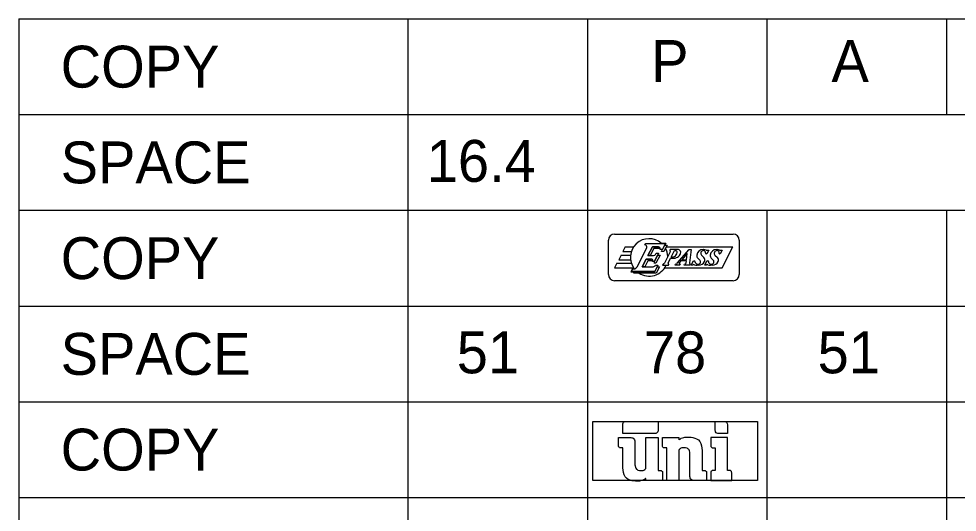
# Model space of a CAD drawing. Extents: x 10268259 to 10268554, y 2141099 to 2141249.
# Drawn here: x 10268318.48 to 10268334.16, y 2141164.78 to 2141173.03 of the extents above; entities that cross this region are included whole.
import ezdxf

# ---------------------------------------------------------------- set-up
doc = ezdxf.new("R2010")
doc.units = 0
for name, color, linetype in [('60', 7, 'Continuous'), ('61', 7, 'Continuous'), ('62', 7, 'Continuous'), ('Default', 7, 'Continuous'), ('GSSign', 7, 'Continuous'), ('TextMisc', 7, 'Continuous')]:
    doc.layers.add(name, color=color, linetype=linetype)

# ---------------------------------------------------------------- blocks, each defined once
blk = doc.blocks.new('block 2_2')
at = {"layer": 'Default'}
for points in [[(19.1, -34.5), (14.6, -34.5), (11, -38.1), (11, -42.5), (11, -42.5), (11, -64.2), (11, -64.2), (11, -64.2), (89.5, -64.2), (89.5, -64.2), (94.1, -64.2), (97.9, -60.4), (97.9, -55.8), (97.9, -55.8), (97.9, -34.5), (97.9, -34.5), (97.9, -34.5), (19.1, -34.5), (19.1, -34.5)], [(19.1, -34.5), (14.6, -34.5), (11, -38.1), (11, -42.5), (11, -42.5), (11, -64.2), (11, -64.2), (11, -64.2), (89.5, -64.2), (89.5, -64.2), (94.1, -64.2), (97.9, -60.4), (97.9, -55.8), (97.9, -55.8), (97.9, -34.5), (97.9, -34.5), (97.9, -34.5), (19.1, -34.5), (19.1, -34.5)], [(268.4, -42.6), (268.4, -38.2), (264.8, -34.5), (260.3, -34.5), (260.3, -34.5), (238.7, -34.5), (238.7, -34.5), (238.7, -34.5), (238.7, -55.9), (238.7, -55.9), (238.7, -60.5), (242.4, -64.3), (247.1, -64.3), (247.1, -64.3), (268.4, -64.3), (268.4, -64.3), (268.4, -64.3), (268.4, -42.6), (268.4, -42.6)], [(268.4, -42.6), (268.4, -38.2), (264.8, -34.5), (260.3, -34.5), (260.3, -34.5), (238.7, -34.5), (238.7, -34.5), (238.7, -34.5), (238.7, -55.9), (238.7, -55.9), (238.7, -60.5), (242.4, -64.3), (247.1, -64.3), (247.1, -64.3), (268.4, -64.3), (268.4, -64.3), (268.4, -64.3), (268.4, -42.6), (268.4, -42.6)], [(97.9, -74.6), (97.9, -74.6), (68, -74.6), (68, -74.6), (68, -74.6), (68, -74.6), (68, -74.6), (68, -74.6), (68, -150.1), (68, -150.1), (65.2, -153.3), (61, -155.4), (56.3, -155.4), (47.8, -155.4), (40.9, -148.5), (40.9, -139.9), (40.9, -139.6), (40.9, -138.9), (40.9, -138.9), (40.9, -138.9), (40.9, -85.6), (40.9, -85.6), (40.9, -79.5), (36, -74.6), (29.9, -74.6), (29.9, -74.6), (12.8, -74.6), (12.8, -74.6), (12.8, -74.6), (11, -74.6), (11, -74.6), (11, -74.6), (0, -74.6), (0, -74.6), (0, -74.6), (0, -93), (0, -93), (0, -96.8), (3.1, -99.8), (6.9, -99.8), (6.9, -99.8), (11, -99.8), (11, -99.8), (11, -99.8), (11, -138.9), (11, -138.9), (11, -138.9), (11.1, -138.9), (11.1, -138.9), (11.1, -169.3), (28.5, -181.4), (48.5, -181.4), (55.6, -181.4), (62.3, -179), (68, -174.8), (68, -174.8), (68, -180.3), (68, -180.3), (68, -180.3), (108.9, -180.3), (108.9, -180.3), (108.9, -180.3), (108.9, -161.9), (108.9, -161.9), (108.9, -158.1), (105.8, -155.1), (102, -155.1), (102, -155.1), (97.9, -155.1), (97.9, -155.1), (97.9, -155.1), (97.9, -74.6), (97.9, -74.6)], [(97.9, -74.6), (97.9, -74.6), (68, -74.6), (68, -74.6), (68, -74.6), (68, -74.6), (68, -74.6), (68, -74.6), (68, -150.1), (68, -150.1), (65.2, -153.3), (61, -155.4), (56.3, -155.4), (47.8, -155.4), (40.9, -148.5), (40.9, -139.9), (40.9, -139.6), (40.9, -138.9), (40.9, -138.9), (40.9, -138.9), (40.9, -85.6), (40.9, -85.6), (40.9, -79.5), (36, -74.6), (29.9, -74.6), (29.9, -74.6), (12.8, -74.6), (12.8, -74.6), (12.8, -74.6), (11, -74.6), (11, -74.6), (11, -74.6), (0, -74.6), (0, -74.6), (0, -74.6), (0, -93), (0, -93), (0, -96.8), (3.1, -99.8), (6.9, -99.8), (6.9, -99.8), (11, -99.8), (11, -99.8), (11, -99.8), (11, -138.9), (11, -138.9), (11, -138.9), (11.1, -138.9), (11.1, -138.9), (11.1, -169.3), (28.5, -181.4), (48.5, -181.4), (55.6, -181.4), (62.3, -179), (68, -174.8), (68, -174.8), (68, -180.3), (68, -180.3), (68, -180.3), (108.9, -180.3), (108.9, -180.3), (108.9, -180.3), (108.9, -161.9), (108.9, -161.9), (108.9, -158.1), (105.8, -155.1), (102, -155.1), (102, -155.1), (97.9, -155.1), (97.9, -155.1), (97.9, -155.1), (97.9, -74.6), (97.9, -74.6)], [(119.3, -155.1), (119.3, -155.1), (119.3, -180.3), (119.3, -180.3), (119.3, -180.3), (149.1, -180.3), (149.1, -180.3), (149.1, -180.3), (149.1, -180.3), (149.1, -180.3), (149.1, -180.3), (149.1, -155.1), (149.1, -155.1), (149.1, -155.1), (149.1, -104.8), (149.1, -104.8), (152, -101.6), (156.1, -99.5), (160.8, -99.5), (169.3, -99.5), (176.3, -106.4), (176.3, -115), (176.3, -115.3), (176.3, -116), (176.3, -116), (176.3, -116), (176.3, -169.3), (176.3, -169.3), (176.3, -175.4), (181.2, -180.3), (187.3, -180.3), (187.3, -180.3), (204.3, -180.3), (204.3, -180.3), (204.3, -180.3), (206.1, -180.3), (206.1, -180.3), (206.1, -180.3), (217.1, -180.3), (217.1, -180.3), (217.1, -180.3), (217.1, -161.9), (217.1, -161.9), (217.1, -158.1), (214.1, -155.1), (210.3, -155.1), (210.3, -155.1), (206.1, -155.1), (206.1, -155.1), (206.1, -155.1), (206.1, -116), (206.1, -116), (206.1, -116), (206, -116), (206, -116), (206, -85.6), (188.7, -73.5), (168.7, -73.5), (161.5, -73.5), (154.8, -75.9), (149.1, -80.1), (149.1, -80.1), (149.1, -74.6), (149.1, -74.6), (149.1, -74.6), (119.3, -74.6), (119.3, -74.6), (119.3, -74.6), (108.3, -74.6), (108.3, -74.6), (108.3, -74.6), (108.3, -93), (108.3, -93), (108.3, -96.8), (111.3, -99.8), (115.1, -99.8), (115.1, -99.8), (119.3, -99.8), (119.3, -99.8), (119.3, -99.8), (119.3, -104.7), (119.3, -104.7), (119.3, -104.7), (119.3, -155.1), (119.3, -155.1)], [(119.3, -155.1), (119.3, -155.1), (119.3, -180.3), (119.3, -180.3), (119.3, -180.3), (149.1, -180.3), (149.1, -180.3), (149.1, -180.3), (149.1, -180.3), (149.1, -180.3), (149.1, -180.3), (149.1, -155.1), (149.1, -155.1), (149.1, -155.1), (149.1, -104.8), (149.1, -104.8), (152, -101.6), (156.1, -99.5), (160.8, -99.5), (169.3, -99.5), (176.3, -106.4), (176.3, -115), (176.3, -115.3), (176.3, -116), (176.3, -116), (176.3, -116), (176.3, -169.3), (176.3, -169.3), (176.3, -175.4), (181.2, -180.3), (187.3, -180.3), (187.3, -180.3), (204.3, -180.3), (204.3, -180.3), (204.3, -180.3), (206.1, -180.3), (206.1, -180.3), (206.1, -180.3), (217.1, -180.3), (217.1, -180.3), (217.1, -180.3), (217.1, -161.9), (217.1, -161.9), (217.1, -158.1), (214.1, -155.1), (210.3, -155.1), (210.3, -155.1), (206.1, -155.1), (206.1, -155.1), (206.1, -155.1), (206.1, -116), (206.1, -116), (206.1, -116), (206, -116), (206, -116), (206, -85.6), (188.7, -73.5), (168.7, -73.5), (161.5, -73.5), (154.8, -75.9), (149.1, -80.1), (149.1, -80.1), (149.1, -74.6), (149.1, -74.6), (149.1, -74.6), (119.3, -74.6), (119.3, -74.6), (119.3, -74.6), (108.3, -74.6), (108.3, -74.6), (108.3, -74.6), (108.3, -93), (108.3, -93), (108.3, -96.8), (111.3, -99.8), (115.1, -99.8), (115.1, -99.8), (119.3, -99.8), (119.3, -99.8), (119.3, -99.8), (119.3, -104.7), (119.3, -104.7), (119.3, -104.7), (119.3, -155.1), (119.3, -155.1)], [(279.4, -161.9), (279.4, -161.9), (279.4, -180.3), (279.4, -180.3), (279.4, -180.3), (227.5, -180.3), (227.5, -180.3), (227.5, -180.3), (227.5, -161.9), (227.5, -161.9), (227.5, -158.1), (230.6, -155.1), (234.4, -155.1), (234.4, -155.1), (238.5, -155.1), (238.5, -155.1), (238.5, -155.1), (238.5, -104.7), (238.5, -104.7), (238.5, -104.7), (238.5, -99.8), (238.5, -99.8), (238.5, -99.8), (234.4, -99.8), (234.4, -99.8), (230.6, -99.8), (227.5, -96.8), (227.5, -93), (227.5, -93), (227.5, -74.6), (227.5, -74.6), (227.5, -74.6), (238.5, -74.6), (238.5, -74.6), (238.5, -74.6), (268.4, -74.6), (268.4, -74.6), (268.4, -74.6), (268.4, -82), (268.4, -82), (268.4, -82), (268.4, -155.1), (268.4, -155.1), (268.4, -155.1), (272.5, -155.1), (272.5, -155.1), (276.3, -155.1), (279.4, -158.1), (279.4, -161.9)], [(279.4, -161.9), (279.4, -161.9), (279.4, -180.3), (279.4, -180.3), (279.4, -180.3), (227.5, -180.3), (227.5, -180.3), (227.5, -180.3), (227.5, -161.9), (227.5, -161.9), (227.5, -158.1), (230.6, -155.1), (234.4, -155.1), (234.4, -155.1), (238.5, -155.1), (238.5, -155.1), (238.5, -155.1), (238.5, -104.7), (238.5, -104.7), (238.5, -104.7), (238.5, -99.8), (238.5, -99.8), (238.5, -99.8), (234.4, -99.8), (234.4, -99.8), (230.6, -99.8), (227.5, -96.8), (227.5, -93), (227.5, -93), (227.5, -74.6), (227.5, -74.6), (227.5, -74.6), (238.5, -74.6), (238.5, -74.6), (238.5, -74.6), (268.4, -74.6), (268.4, -74.6), (268.4, -74.6), (268.4, -82), (268.4, -82), (268.4, -82), (268.4, -155.1), (268.4, -155.1), (268.4, -155.1), (272.5, -155.1), (272.5, -155.1), (276.3, -155.1), (279.4, -158.1), (279.4, -161.9)]]:
    blk.add_open_spline(points, degree=3, dxfattribs=at)

msp = doc.modelspace()

# ---------------------------------------------------------------- linework, layer by layer
at = {"layer": '60'}
for p, q in [((10268318.48, 2141173.028), (10268393.98, 2141173.028)), ((10268318.48, 2141173.028), (10268318.48, 2141157.028)), ((10268324.98, 2141173.028), (10268324.98, 2141157.028)), ((10268327.98, 2141173.028), (10268327.98, 2141157.028)), ((10268330.98, 2141173.028), (10268330.98, 2141171.428)), ((10268333.98, 2141173.028), (10268333.98, 2141171.428)), ((10268318.48, 2141169.828), (10268393.98, 2141169.828)), ((10268330.98, 2141169.828), (10268330.98, 2141166.628)), ((10268333.98, 2141169.828), (10268333.98, 2141166.628)), ((10268318.48, 2141166.628), (10268393.98, 2141166.628)), ((10268330.98, 2141166.628), (10268330.98, 2141163.428)), ((10268333.98, 2141166.628), (10268333.98, 2141163.428))]:
    msp.add_line(p, q, dxfattribs=at)
at = {"layer": '61'}
for p, q in [((10268318.48, 2141171.428), (10268393.98, 2141171.428)), ((10268318.48, 2141168.228), (10268393.98, 2141168.228)), ((10268318.48, 2141165.028), (10268393.98, 2141165.028))]:
    msp.add_line(p, q, dxfattribs=at)
at = {"layer": '62'}
for p, q in [((10268328.435, 2141169.431), (10268330.414, 2141169.431)), ((10268328.331, 2141168.754), (10268328.331, 2141169.327)), ((10268328.614, 2141169.216), (10268328.574, 2141169.138)), ((10268328.614, 2141169.216), (10268328.754, 2141169.216)), ((10268328.811, 2141168.884), (10268328.973, 2141169.202)), ((10268328.942, 2141169.248), (10268328.955, 2141169.275)), ((10268328.955, 2141169.275), (10268329.287, 2141169.275)), ((10268329.068, 2141169.216), (10268328.993, 2141169.07)), ((10268328.993, 2141169.07), (10268329.068, 2141169.216)), ((10268328.993, 2141169.07), (10268329.068, 2141169.216)), ((10268329.167, 2141169.216), (10268329.068, 2141169.216)), ((10268329.068, 2141169.216), (10268329.167, 2141169.216)), ((10268329.068, 2141169.216), (10268329.167, 2141169.216)), ((10268329.216, 2141169.278), (10268329.292, 2141169.278)), ((10268329.287, 2141169.275), (10268329.234, 2141169.17)), ((10268329.234, 2141169.17), (10268329.272, 2141169.245)), ((10268329.234, 2141169.17), (10268329.272, 2141169.245)), ((10268329.312, 2141169.245), (10268329.258, 2141169.141)), ((10268329.312, 2141169.245), (10268329.258, 2141169.141)), ((10268329.272, 2141169.245), (10268329.312, 2141169.245)), ((10268329.272, 2141169.245), (10268329.312, 2141169.245)), ((10268329.292, 2141169.278), (10268329.275, 2141169.245)), ((10268329.297, 2141169.216), (10268330.411, 2141169.216)), ((10268330.232, 2141168.864), (10268330.411, 2141169.216)), ((10268330.518, 2141169.327), (10268330.518, 2141168.754)), ((10268328.544, 2141169.079), (10268328.505, 2141169.001)), ((10268328.544, 2141169.079), (10268328.702, 2141169.079)), ((10268328.574, 2141169.138), (10268328.716, 2141169.138)), ((10268328.993, 2141169.07), (10268329.086, 2141169.07)), ((10268329.032, 2141169.07), (10268328.993, 2141169.07)), ((10268329.032, 2141169.07), (10268328.993, 2141169.07)), ((10268329.092, 2141169.187), (10268329.032, 2141169.07)), ((10268329.092, 2141169.187), (10268329.032, 2141169.07)), ((10268329.198, 2141169.187), (10268329.092, 2141169.187)), ((10268329.198, 2141169.187), (10268329.092, 2141169.187)), ((10268329.169, 2141169.109), (10268329.1, 2141168.972)), ((10268329.1, 2141168.972), (10268329.154, 2141169.079)), ((10268329.1, 2141168.972), (10268329.154, 2141169.079)), ((10268329.121, 2141169.091), (10268329.13, 2141169.109)), ((10268329.194, 2141169.079), (10268329.124, 2141168.943)), ((10268329.194, 2141169.079), (10268329.124, 2141168.943)), ((10268329.13, 2141169.109), (10268329.169, 2141169.109)), ((10268329.154, 2141169.079), (10268329.194, 2141169.079)), ((10268329.154, 2141169.079), (10268329.194, 2141169.079)), ((10268329.234, 2141169.17), (10268329.195, 2141169.17)), ((10268329.219, 2141169.17), (10268329.234, 2141169.17)), ((10268329.219, 2141169.17), (10268329.234, 2141169.17)), ((10268329.258, 2141169.141), (10268329.219, 2141169.141)), ((10268329.258, 2141169.141), (10268329.219, 2141169.141)), ((10268329.366, 2141169.135), (10268329.27, 2141168.945)), ((10268329.366, 2141169.172), (10268329.361, 2141169.162)), ((10268329.486, 2141169.172), (10268329.366, 2141169.172)), ((10268329.381, 2141169.044), (10268329.437, 2141169.153)), ((10268329.401, 2141169.044), (10268329.381, 2141169.044)), ((10268329.437, 2141169.153), (10268329.455, 2141169.153)), ((10268329.483, 2141168.943), (10268329.682, 2141169.172)), ((10268329.649, 2141169.105), (10268329.56, 2141169.002)), ((10268329.636, 2141169.002), (10268329.649, 2141169.105)), ((10268329.682, 2141169.172), (10268329.717, 2141169.172)), ((10268329.717, 2141169.172), (10268329.688, 2141168.947)), ((10268329.888, 2141169.078), (10268329.929, 2141169.037)), ((10268329.915, 2141169.172), (10268329.922, 2141169.172)), ((10268329.927, 2141169.153), (10268329.919, 2141169.153)), ((10268329.977, 2141169.101), (10268329.967, 2141169.101)), ((10268330.008, 2141169.162), (10268329.977, 2141169.101)), ((10268329.993, 2141169.162), (10268330.008, 2141169.162)), ((10268330.112, 2141169.078), (10268330.153, 2141169.037)), ((10268330.139, 2141169.172), (10268330.147, 2141169.172)), ((10268330.152, 2141169.153), (10268330.143, 2141169.153)), ((10268330.201, 2141169.101), (10268330.191, 2141169.101)), ((10268330.232, 2141169.162), (10268330.201, 2141169.101)), ((10268330.218, 2141169.162), (10268330.232, 2141169.162)), ((10268328.475, 2141168.943), (10268328.435, 2141168.864)), ((10268328.475, 2141168.943), (10268328.716, 2141168.943)), ((10268328.505, 2141169.001), (10268328.702, 2141169.001)), ((10268328.963, 2141169.011), (10268328.898, 2141168.884)), ((10268328.898, 2141168.884), (10268328.963, 2141169.011)), ((10268328.898, 2141168.884), (10268328.963, 2141169.011)), ((10268328.898, 2141168.884), (10268329.078, 2141168.884)), ((10268328.938, 2141168.884), (10268328.898, 2141168.884)), ((10268328.938, 2141168.884), (10268328.898, 2141168.884)), ((10268328.988, 2141168.982), (10268328.938, 2141168.884)), ((10268328.988, 2141168.982), (10268328.938, 2141168.884)), ((10268329.049, 2141169.011), (10268328.963, 2141169.011)), ((10268328.963, 2141169.011), (10268329.045, 2141169.011)), ((10268328.963, 2141169.011), (10268329.045, 2141169.011)), ((10268329.074, 2141168.981), (10268328.988, 2141168.982)), ((10268329.074, 2141168.981), (10268328.988, 2141168.982)), ((10268329.1, 2141168.972), (10268329.07, 2141168.972)), ((10268329.094, 2141168.972), (10268329.1, 2141168.972)), ((10268329.094, 2141168.972), (10268329.1, 2141168.972)), ((10268329.124, 2141168.943), (10268329.095, 2141168.943)), ((10268329.124, 2141168.943), (10268329.095, 2141168.943)), ((10268329.16, 2141168.91), (10268329.107, 2141168.806)), ((10268329.107, 2141168.806), (10268329.145, 2141168.881)), ((10268329.107, 2141168.806), (10268329.145, 2141168.881)), ((10268329.121, 2141168.91), (10268329.16, 2141168.91)), ((10268329.185, 2141168.881), (10268329.131, 2141168.777)), ((10268329.185, 2141168.881), (10268329.131, 2141168.777)), ((10268329.145, 2141168.881), (10268329.185, 2141168.881)), ((10268329.145, 2141168.881), (10268329.185, 2141168.881)), ((10268329.246, 2141168.926), (10268329.237, 2141168.908)), ((10268329.237, 2141168.908), (10268329.335, 2141168.908)), ((10268329.331, 2141168.945), (10268329.371, 2141169.025)), ((10268329.335, 2141168.908), (10268329.34, 2141168.919)), ((10268329.371, 2141169.025), (10268329.401, 2141169.025)), ((10268329.447, 2141168.908), (10268329.455, 2141168.925)), ((10268329.525, 2141168.908), (10268329.447, 2141168.908)), ((10268329.543, 2141168.983), (10268329.515, 2141168.95)), ((10268329.531, 2141168.92), (10268329.525, 2141168.908)), ((10268329.634, 2141168.983), (10268329.543, 2141168.983)), ((10268329.56, 2141169.002), (10268329.636, 2141169.002)), ((10268329.597, 2141168.908), (10268329.606, 2141168.925)), ((10268329.695, 2141168.908), (10268329.597, 2141168.908)), ((10268329.629, 2141168.947), (10268329.634, 2141168.983)), ((10268329.7, 2141168.918), (10268329.695, 2141168.908)), ((10268329.717, 2141168.913), (10268329.752, 2141168.983)), ((10268329.741, 2141168.913), (10268329.717, 2141168.913)), ((10268329.752, 2141168.983), (10268329.768, 2141168.983)), ((10268329.843, 2141168.908), (10268329.814, 2141168.908)), ((10268329.822, 2141168.928), (10268329.832, 2141168.928)), ((10268329.86, 2141168.995), (10268329.825, 2141169.03)), ((10268329.942, 2141168.913), (10268329.977, 2141168.983)), ((10268329.965, 2141168.913), (10268329.942, 2141168.913)), ((10268329.977, 2141168.983), (10268329.993, 2141168.983)), ((10268330.068, 2141168.908), (10268330.038, 2141168.908)), ((10268330.046, 2141168.928), (10268330.057, 2141168.928)), ((10268330.085, 2141168.995), (10268330.05, 2141169.03)), ((10268328.435, 2141168.864), (10268328.754, 2141168.864)), ((10268328.734, 2141168.857), (10268328.705, 2141168.799)), ((10268328.705, 2141168.799), (10268328.766, 2141168.799)), ((10268328.716, 2141168.806), (10268328.738, 2141168.849)), ((10268329.107, 2141168.806), (10268328.716, 2141168.806)), ((10268328.734, 2141168.857), (10268328.759, 2141168.857)), ((10268328.738, 2141168.849), (10268328.755, 2141168.849)), ((10268328.755, 2141168.777), (10268328.77, 2141168.806)), ((10268328.755, 2141168.777), (10268328.77, 2141168.806)), ((10268329.131, 2141168.777), (10268328.755, 2141168.777)), ((10268329.131, 2141168.777), (10268328.755, 2141168.777)), ((10268328.77, 2141168.806), (10268329.107, 2141168.806)), ((10268328.77, 2141168.806), (10268329.107, 2141168.806)), ((10268329.271, 2141168.864), (10268330.232, 2141168.864)), ((10268330.414, 2141168.65), (10268328.435, 2141168.65))]:
    msp.add_line(p, q, dxfattribs=at)
for points in [[(10268329.216, 2141169.278), (10268329.292, 2141169.278), (10268329.275, 2141169.245), (10268329.272, 2141169.245), (10268329.287, 2141169.275), (10268329.219, 2141169.275)], [(10268328.759, 2141168.857), (10268328.734, 2141168.857), (10268328.705, 2141168.799), (10268328.766, 2141168.799), (10268328.77, 2141168.806), (10268328.716, 2141168.806), (10268328.739, 2141168.849), (10268328.755, 2141168.849), (10268328.764, 2141168.85)]]:
    msp.add_lwpolyline(points, close=True, dxfattribs=at)
for centre, radius, start, end in [((10268328.435, 2141169.327), 0.104, 90, 180), ((10268329.012, 2141169.04), 0.313, 48.5904, 217.4727), ((10268330.414, 2141169.327), 0.104, 0, 90), ((10268328.944, 2141169.216), 0.0322, 332.9998, 93.8045), ((10268329.167, 2141169.185), 0.0313, 332.2089, 90), ((10268329.167, 2141169.185), 0.0313, 3.5833, 90), ((10268329.167, 2141169.185), 0.0313, 3.5833, 90), ((10268329.012, 2141169.04), 0.313, 2.4236, 29.2771), ((10268329.086, 2141169.109), 0.0391, 270, 332.9883), ((10268329.192, 2141169.155), 0.0313, 332.2089, 27.9127), ((10268329.192, 2141169.155), 0.0313, 332.2089, 27.9127), ((10268329.369, 2141169.157), 0.00977, 152.9784, 231.1602), ((10268329.356, 2141169.14), 0.0117, 333.0027, 51.1602), ((10268329.401, 2141169.113), 0.0684, 270, 302.4206), ((10268329.401, 2141169.22), 0.195, 270, 296.6431), ((10268329.385, 2141169.137), 0.0977, 302.4206, 351.076), ((10268329.455, 2141169.126), 0.0264, 351.076, 90), ((10268329.486, 2141169.116), 0.0557, 29.4315, 90), ((10268329.444, 2141169.133), 0.0977, 296.6431, 344.7074), ((10268329.492, 2141169.12), 0.0488, 344.7074, 29.4315), ((10268329.915, 2141169.065), 0.107, 90, 172.3089), ((10268329.866, 2141169.071), 0.0586, 172.3089, 225), ((10268329.919, 2141169.109), 0.0439, 90, 225), ((10268329.922, 2141169.074), 0.0977, 64.0896, 90), ((10268329.927, 2141169.123), 0.0293, 345.6915, 90), ((10268329.887, 2141168.995), 0.0586, 334.95, 45), ((10268329.967, 2141169.113), 0.0117, 165.6915, 270), ((10268329.978, 2141169.189), 0.0293, 244.0896, 292.0347), ((10268329.993, 2141169.151), 0.0117, 90, 112.0347), ((10268330.091, 2141169.071), 0.0586, 172.3089, 225), ((10268330.139, 2141169.065), 0.107, 90, 172.3089), ((10268330.143, 2141169.109), 0.0439, 90, 225), ((10268330.147, 2141169.074), 0.0977, 64.0896, 90), ((10268330.152, 2141169.123), 0.0293, 345.6915, 90), ((10268330.112, 2141168.995), 0.0586, 334.95, 45), ((10268330.191, 2141169.113), 0.0117, 165.6915, 270), ((10268330.202, 2141169.189), 0.0293, 244.0896, 292.0347), ((10268330.218, 2141169.151), 0.0117, 90, 112.0347), ((10268328.755, 2141168.912), 0.0625, 270, 332.9991), ((10268329.012, 2141169.04), 0.313, 237.5383, 335.047), ((10268329.049, 2141168.986), 0.0254, 350.3502, 98.3344), ((10268329.049, 2141168.986), 0.0254, 350.3502, 98.3344), ((10268329.049, 2141168.986), 0.0254, 327.421, 90), ((10268329.078, 2141168.933), 0.0488, 270, 332.5096), ((10268329.074, 2141168.956), 0.0254, 327.421, 37.9799), ((10268329.074, 2141168.956), 0.0254, 327.421, 37.9799), ((10268329.263, 2141168.917), 0.0195, 106.4317, 152.9742), ((10268329.252, 2141168.954), 0.0195, 286.4317, 332.9959), ((10268329.34, 2141168.941), 0.00977, 152.9884, 244.7832), ((10268329.331, 2141168.923), 0.00977, 333.0239, 64.7832), ((10268329.464, 2141168.921), 0.00977, 102.7162, 153.0239), ((10268329.453, 2141168.968), 0.0391, 282.7162, 318.9966), ((10268329.522, 2141168.944), 0.00977, 138.9824, 268.6869), ((10268329.522, 2141168.924), 0.00977, 332.9784, 88.6869), ((10268329.615, 2141168.921), 0.00977, 99.2397, 153.0239), ((10268329.61, 2141168.95), 0.0195, 279.2397, 352.5632), ((10268329.703, 2141168.945), 0.0156, 172.5884, 241.8673), ((10268329.691, 2141168.923), 0.00977, 332.9784, 61.8673), ((10268329.759, 2141168.893), 0.0273, 64.3795, 133.1892), ((10268329.768, 2141168.973), 0.00977, 358.6664, 90), ((10268329.814, 2141169.006), 0.0977, 244.3795, 270), ((10268329.822, 2141168.972), 0.0439, 178.6665, 270), ((10268329.832, 2141168.967), 0.0391, 270, 45), ((10268329.843, 2141169.016), 0.107, 270, 334.95), ((10268329.984, 2141168.893), 0.0273, 64.3795, 133.1892), ((10268329.993, 2141168.973), 0.00977, 358.6664, 90), ((10268330.038, 2141169.006), 0.0977, 244.3795, 270), ((10268330.046, 2141168.972), 0.0439, 178.6665, 270), ((10268330.057, 2141168.967), 0.0391, 270, 45), ((10268330.068, 2141169.016), 0.107, 270, 334.95), ((10268328.435, 2141168.754), 0.104, 180, 270), ((10268330.414, 2141168.754), 0.104, 270, 0)]:
    msp.add_arc(centre, radius, start, end, dxfattribs=at)
at = {"layer": 'GSSign'}
msp.add_lwpolyline([(10268328.071, 2141166.3), (10268330.823, 2141166.3), (10268330.823, 2141165.31), (10268328.071, 2141165.31)], close=True, dxfattribs=at)

# ---------------------------------------------------------------- block references
at = {"layer": 'Default', "xscale": 0.006787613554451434, "yscale": 0.006787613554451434}
msp.add_blockref('block 2_2', (10268328.498, 2141166.534), dxfattribs=at)

# ---------------------------------------------------------------- texts
at = {"layer": '62'}
for s, p in [('P', (10268329.047, 2141171.973)), ('A', (10268332.059, 2141171.973)), ('16.4', (10268325.297, 2141170.303)), ('51', (10268325.798, 2141167.103)), ('78', (10268328.925, 2141167.103)), ('51', (10268331.827, 2141167.103))]:
    msp.add_text(s, height=0.7, dxfattribs=at).set_placement(p)
at = {"layer": 'TextMisc'}
for s, p in [('COPY', (10268319.18, 2141171.878)), ('SPACE', (10268319.18, 2141170.278)), ('COPY', (10268319.18, 2141168.678)), ('SPACE', (10268319.18, 2141167.078)), ('COPY', (10268319.18, 2141165.478))]:
    msp.add_text(s, height=0.7, dxfattribs=at).set_placement(p)

doc.saveas('drawing.dxf')
